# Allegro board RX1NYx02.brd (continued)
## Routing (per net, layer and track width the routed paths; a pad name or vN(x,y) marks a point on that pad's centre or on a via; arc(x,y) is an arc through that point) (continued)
PE_CPU_OCP_13_DN: length 58.9
  TOP w0.127: 237.46,-26.52 237.58,-26.39 239.44,-26.39 241.73,-28.68 242.76,-28.68 243.33,-28.11 243.33,-27.62 243.17,-26.72 243.33,-25.8 243.33,-25.46 242.69,-23.68 242.69,-21.4 242.28,-20.3 242.14,-19.5 242.14,-17.9 245.08,-14.96 245.34,-14.96 246.24,-15.12 248.1,-14.79 250.35,-15.19 252.6,-14.8 254.85,-15.19 257.11,-14.8 259.36,-15.19 260.65,-14.96 260.91,-14.96 261.87,-15.13 264.12,-14.74 266.37,-15.13 268.62,-14.74 269.91,-14.96 270.51,-14.96 270.97,-15.42 271.63,-15.42 272.37,-16.16 273.13,-16.16 273.69,-16.06 274.24,-16.16 274.78,-16.16 274.93,-16.31 P_OCP2.B59
  TOP w0.152: 237.46,-26.52 P_CPU_OCP_13_N.1
PE_CPU_OCP_13_DP: length 58.9
  TOP w0.127: 237.46,-25.96 237.58,-26.09 239.57,-26.09 241.86,-28.38 242.63,-28.38 243.03,-27.98 243.03,-27.65 242.86,-26.72 243.03,-25.78 243.03,-25.51 242.38,-23.74 242.38,-21.45 241.99,-20.38 241.84,-19.52 241.84,-17.78 244.96,-14.66 245.37,-14.66 246.24,-14.81 248.1,-14.49 250.35,-14.88 252.6,-14.49 254.85,-14.88 257.11,-14.49 259.36,-14.88 260.62,-14.66 260.93,-14.66 261.87,-14.82 264.12,-14.43 266.37,-14.82 268.62,-14.43 269.94,-14.66 270.64,-14.66 271.09,-15.12 271.75,-15.12 272.49,-15.85 273.1,-15.85 273.69,-15.75 274.27,-15.85 274.78,-15.85 274.93,-15.71 P_OCP2.B60
  TOP w0.152: 237.46,-25.96 P_CPU_OCP_13_P.1
PE_CPU_OCP_14_DN: length 58.9
  TOP w0.127: 257.69,-13.25 257.11,-13.14 256.51,-13.25 ; P_OCP2.B62 274.93,-14.51 274.78,-14.36 273.95,-14.36 273.53,-13.95 271.81,-13.95 271.2,-13.34 270.83,-13.34 ; 257.88,-13.28 259.36,-13.54 260.51,-13.34 261.05,-13.34 261.87,-13.48 264.12,-13.09 264.85,-13.21 ; 265.09,-13.26 266.37,-13.48 268.14,-13.17 ; 231.46,-9.09 231.59,-9.22 230.83,-13.55 231.02,-15.15 231.84,-15.97 234.3,-15.97 236.93,-13.34 237.44,-13.34 238.57,-13.14 240.82,-13.54 243.07,-13.14 244.19,-13.34 245.48,-13.34 246.24,-13.47 248.1,-13.14 250.35,-13.54 252.6,-13.14 254.85,-13.54 256.3,-13.29 ; 268.34,-13.14 268.62,-13.09 270.05,-13.34 270.62,-13.34
  TOP w0.152: P_CPU_OCP_14_N.1 231.46,-9.09 ; 268.14,-13.17 268.34,-13.14 ; 257.69,-13.25 257.88,-13.28 ; 264.85,-13.21 265.09,-13.26 ; 270.62,-13.34 270.83,-13.34 ; 256.3,-13.29 256.51,-13.25
PE_CPU_OCP_14_DP: length 58.9
  TOP w0.127: 270.62,-12.91 270.5,-13.03 270.08,-13.03 268.62,-12.78 268.42,-12.81 268.28,-12.71 ; 256.43,-12.86 256.54,-12.94 257.11,-12.83 257.63,-12.93 257.77,-12.82 ; 264.95,-12.79 264.8,-12.9 264.12,-12.78 261.87,-13.17 261.08,-13.03 260.48,-13.03 259.36,-13.23 258.08,-13.01 257.97,-12.86 ; 265.15,-12.83 265.25,-12.98 266.37,-13.17 267.97,-12.89 268.08,-12.74 ; 270.83,-12.91 270.95,-13.03 271.32,-13.03 271.93,-13.64 273.66,-13.64 274.07,-14.05 274.78,-14.05 274.93,-13.91 P_OCP2.B63 ; 232.02,-9.09 231.89,-9.22 231.14,-13.56 231.31,-15.01 231.97,-15.67 234.18,-15.67 236.81,-13.03 237.41,-13.03 238.57,-12.83 240.82,-13.23 243.07,-12.83 244.22,-13.03 245.51,-13.03 246.24,-13.16 248.1,-12.83 250.35,-13.23 252.6,-12.83 254.85,-13.23 256.17,-13 256.25,-12.89
  TOP w0.152: 256.25,-12.89 256.43,-12.86 ; P_CPU_OCP_14_P.1 232.02,-9.09 ; 268.08,-12.74 268.28,-12.71 ; 264.95,-12.79 265.15,-12.83 ; 270.62,-12.91 270.83,-12.91 ; 257.77,-12.82 257.97,-12.86
PE_CPU_OCP_15_DN: length 58.9
  TOP w0.127: 263.84,-8.22 263.92,-8.3 263.92,-8.64 264.22,-8.94 264.78,-8.94 265.41,-8.84 266.03,-8.94 266.46,-8.94 267.58,-8.75 268.71,-8.94 269.48,-8.94 269.61,-9.07 269.61,-9.78 269.41,-9.99 268.66,-9.99 267.58,-9.8 266.5,-9.99 266.24,-9.99 265.45,-10.12 264.66,-9.99 264.25,-9.99 263.94,-10.29 263.94,-10.68 263.82,-10.81 ; 266.81,-11.84 266.67,-11.74 265.95,-11.86 264.8,-11.66 264.25,-11.66 263.94,-11.36 263.94,-11.14 263.82,-11.01 ; 254.88,-9.86 254.75,-9.73 254.75,-9.32 253.55,-8.11 253.25,-6.4 253.36,-5.81 253.52,-5.68 254.26,-5.68 254.58,-6 254.59,-6.07 254.51,-6.56 254.51,-7.5 254.87,-7.86 255.71,-7.9 256.16,-7.53 256.28,-6.86 256.16,-6.18 256.16,-6.1 256.71,-5.54 257.03,-5.54 258.18,-5.75 259.33,-5.54 260.76,-5.54 261.91,-5.75 263.06,-5.54 263.88,-5.54 264.95,-5.73 266.03,-5.54 266.22,-5.54 266.4,-5.72 266.4,-6.08 266.46,-6.44 266.4,-6.81 266.4,-7.06 266.19,-7.27 266.09,-7.27 265.33,-7.14 264.58,-7.27 264.22,-7.27 263.92,-7.57 263.92,-7.84 263.84,-7.92 ; 272.71,-12.42 272.89,-12.42 273.03,-12.56 274.78,-12.56 274.93,-12.71 P_OCP2.B65 ; 267.01,-11.81 267.12,-11.66 267.75,-11.55 268.4,-11.66 268.91,-11.66 270.07,-11.86 270.86,-11.73 271.01,-11.83 ; 272.57,-12.27 272.57,-12.09 272.14,-11.66 271.98,-11.66 271.6,-11.6 271.31,-11.65 271.21,-11.79
  TOP w0.152: 263.84,-7.92 263.84,-8.22 ; 271.01,-11.83 271.21,-11.79 ; 263.82,-10.81 263.82,-11.01 ; P_CPU_OCP_15_N.1 254.88,-9.86 ; 272.57,-12.27 272.71,-12.42 ; 266.81,-11.84 267.01,-11.81
PE_CPU_OCP_15_DP: length 58.9
  TOP w0.127: P_OCP2.B66 274.93,-12.11 274.78,-12.25 273.16,-12.25 273.02,-12.11 ; 266.96,-11.38 267.75,-11.24 268.43,-11.36 268.94,-11.36 270.07,-11.56 270.97,-11.4 ; 264.22,-7.94 264.22,-7.7 264.35,-7.57 264.6,-7.57 265.33,-7.45 266.06,-7.57 266.32,-7.57 266.7,-7.19 266.7,-6.84 266.77,-6.44 266.7,-6.05 266.7,-5.59 266.35,-5.24 266,-5.24 264.95,-5.42 263.91,-5.24 263.04,-5.24 261.91,-5.44 260.78,-5.24 259.3,-5.24 258.18,-5.44 257.05,-5.24 256.59,-5.24 255.85,-5.97 255.85,-6.2 255.97,-6.86 255.88,-7.37 255.61,-7.59 255,-7.56 254.81,-7.37 254.81,-6.59 254.9,-6.07 254.87,-5.85 254.39,-5.37 253.41,-5.37 253.07,-5.65 252.95,-6.4 253.27,-8.26 254.45,-9.44 254.45,-9.73 254.32,-9.86 ; 271.12,-11.37 271.6,-11.29 272.01,-11.36 272.26,-11.36 272.88,-11.97 ; 264.22,-8.19 264.22,-8.51 264.35,-8.64 264.76,-8.64 265.41,-8.53 266.05,-8.64 266.43,-8.64 267.58,-8.44 268.74,-8.64 269.61,-8.64 269.91,-8.94 269.91,-9.91 269.53,-10.29 268.63,-10.29 267.58,-10.11 266.52,-10.29 266.27,-10.29 265.45,-10.43 264.64,-10.29 264.38,-10.29 264.25,-10.42 264.25,-10.8 ; 266.76,-11.41 265.95,-11.56 264.83,-11.36 264.38,-11.36 264.25,-11.23 264.25,-11.01
  TOP w0.152: P_CPU_OCP_15_P.1 254.32,-9.86 ; 270.97,-11.4 271.12,-11.37 ; 264.22,-7.94 264.22,-8.19 ; 264.25,-10.8 264.25,-11.01 ; 266.76,-11.41 266.96,-11.38 ; 272.88,-11.97 273.02,-12.11
PE_OCP_CPU_0_DN: length 104.7
  BOTTOM w0.127: 61.25,-19.6 64.2,-19.08 66.12,-19.42 ; 69.48,-25.91 69.35,-25.78 69.35,-25.36 69.72,-23.25 71.25,-21.72 72.76,-21.46 75.29,-21.91 ; 75.6,-18.89 76.58,-18.72 78.94,-19.13 79.82,-20.01 79.82,-21.07 79.11,-21.78 76.86,-22.18 75.53,-21.95 ; 66.36,-19.46 66.87,-19.55 69.37,-19.11 71.87,-19.55 75.39,-18.93 ; P_OCP1.A17 3.15,-31.5 3.3,-31.64 3.95,-31.64 4.66,-31.52 8.75,-32.24 12.46,-31.59 13.59,-31.79 15.87,-31.39 18.5,-31.85 20.93,-31.42 23.43,-31.86 27.22,-31.19 29.55,-31.6 39.02,-29.93 40.57,-30.21 44.04,-29.6 45.59,-28.05 46.42,-23.39 47.84,-21.97 54.32,-20.82 ; 61.07,-19.63 54.53,-20.79
  BOTTOM w0.152: 54.53,-20.79 54.32,-20.82 ; 75.29,-21.91 75.53,-21.95 ; 66.36,-19.46 66.12,-19.42 ; 75.6,-18.89 75.39,-18.93 ; 61.25,-19.6 61.07,-19.63 ; P_OCP_CPU_0_N.1 69.48,-25.91
PE_OCP_CPU_0_DP: length 104.7
  BOTTOM w0.127: 75.48,-19.35 75.33,-19.25 71.87,-19.86 69.37,-19.42 66.87,-19.86 66.41,-19.78 66.26,-19.88 ; 54.38,-21.23 54.25,-21.15 47.99,-22.25 46.7,-23.54 45.88,-28.19 44.19,-29.88 40.57,-30.52 39.02,-30.24 29.55,-31.91 27.22,-31.5 23.43,-32.17 20.93,-31.73 18.5,-32.16 15.87,-31.7 13.59,-32.1 12.46,-31.9 8.75,-32.55 4.66,-31.83 3.98,-31.95 3.3,-31.95 3.15,-32.1 P_OCP1.A18 ; 61.32,-20.03 61.42,-19.88 64.2,-19.39 65.96,-19.7 66.06,-19.85 ; 68.92,-25.91 69.05,-25.78 69.05,-25.33 69.44,-23.1 71.1,-21.44 72.76,-21.15 75.26,-21.59 75.4,-21.49 ; 61.12,-20.06 60.97,-19.96 54.7,-21.07 54.61,-21.19 ; 75.68,-19.32 75.78,-19.17 76.58,-19.03 78.8,-19.42 79.51,-20.14 79.51,-20.95 78.96,-21.5 76.86,-21.87 75.71,-21.67 75.6,-21.52
  BOTTOM w0.152: 75.68,-19.32 75.48,-19.35 ; 66.26,-19.88 66.06,-19.85 ; 75.4,-21.49 75.6,-21.52 ; 61.32,-20.03 61.12,-20.06 ; P_OCP_CPU_0_P.1 68.92,-25.91 ; 54.61,-21.19 54.38,-21.23
PE_OCP_CPU_1_DN: length 104.7
  BOTTOM w0.127: 86.68,-30.86 86.58,-31.01 85.9,-31.13 80.46,-30.17 78.58,-29.84 77.38,-30.05 74.88,-29.61 72.38,-30.05 69.88,-29.61 67.37,-30.05 66.65,-29.92 66.55,-29.77 ; 48.88,-29.96 48.77,-30.11 46.79,-30.46 40.19,-31.62 38.66,-31.36 28.42,-33.16 27.15,-32.94 23.92,-33.51 20.9,-32.98 18.52,-33.4 16.3,-33.01 15.84,-33.01 9.69,-34.09 6.05,-33.44 5.06,-33.44 4.39,-33.33 3.73,-33.44 3.3,-33.44 3.15,-33.3 P_OCP1.A20 ; 49.08,-29.93 49.22,-30.03 50.39,-29.83 51.11,-29.83 52.37,-30.05 54.87,-29.61 55.74,-29.76 55.89,-29.66 ; 66.35,-29.74 66.2,-29.84 64.87,-29.61 62.37,-30.05 59.87,-29.61 59.25,-29.72 59.15,-29.65 ; 91.78,-20.58 91.91,-20.7 91.91,-21.16 90.58,-28.79 87.72,-30.8 87.03,-30.93 86.88,-30.82 ; 58.87,-29.69 58.8,-29.79 57.37,-30.05 56.19,-29.84 56.09,-29.69
  BOTTOM w0.152: 59.15,-29.65 58.87,-29.69 ; 49.08,-29.93 48.88,-29.96 ; 86.88,-30.82 86.68,-30.86 ; 66.55,-29.77 66.35,-29.74 ; 56.09,-29.69 55.89,-29.66 ; P_OCP_CPU_1_N.1 91.78,-20.58
PE_OCP_CPU_1_DP: length 104.7
  BOTTOM w0.127: 86.96,-31.25 87.84,-31.09 90.86,-28.97 92.21,-21.18 92.21,-20.7 92.34,-20.58 ; 58.93,-30.08 57.37,-30.36 55.99,-30.11 ; 66.28,-30.16 64.87,-29.91 62.37,-30.36 59.87,-29.91 59.21,-30.03 ; 66.45,-30.19 67.37,-30.36 69.88,-29.91 72.38,-30.36 74.88,-29.91 77.38,-30.36 78.58,-30.14 85.9,-31.43 86.72,-31.29 ; 49.12,-30.36 50.42,-30.13 51.09,-30.13 52.37,-30.36 54.87,-29.91 55.82,-30.08 ; 48.95,-30.39 40.19,-31.93 38.66,-31.66 28.42,-33.47 27.15,-33.25 23.92,-33.82 20.9,-33.29 18.52,-33.71 16.27,-33.31 15.86,-33.31 9.69,-34.4 6.03,-33.75 5.03,-33.75 4.39,-33.64 3.76,-33.75 3.3,-33.75 3.15,-33.9 P_OCP1.A21
  BOTTOM w0.152: P_OCP_CPU_1_P.1 92.34,-20.58 ; 49.12,-30.36 48.95,-30.39 ; 66.45,-30.19 66.28,-30.16 ; 55.99,-30.11 55.82,-30.08 ; 59.21,-30.03 58.93,-30.08 ; 86.96,-31.25 86.72,-31.29
PE_OCP_CPU_2_DN: length 104.8
  BOTTOM w0.127: 74.91,-42.77 74.79,-42.89 74.2,-42.89 71.44,-43.37 70.4,-44.41 70.4,-44.87 70.31,-45.37 70.56,-46.8 70.56,-47 69.93,-47.64 69.02,-47.64 68.6,-47.22 68.38,-45.91 68.38,-45.47 67.91,-42.81 68.35,-40.3 67.91,-37.8 68.45,-34.73 68.2,-33.31 66.38,-31.49 64.19,-31.1 61.69,-31.55 59.19,-31.1 56.69,-31.55 54.18,-31.1 51.68,-31.55 50.43,-31.32 49.7,-31.32 40.12,-33.01 38.83,-32.79 37.37,-33.04 34.87,-35.54 34.87,-38.77 32.36,-41.28 30.96,-41.53 28.69,-41.13 27.2,-41.39 24.76,-40.97 21.45,-41.54 18.68,-41.06 15.85,-41.56 13.2,-41.09 7.9,-35.79 4.28,-35.15 3.65,-35.26 3.32,-35.26 3.15,-35.1 P_OCP1.A23
  BOTTOM w0.152: 74.91,-42.77 P_OCP_CPU_2_N.1
PE_OCP_CPU_2_DP: length 104.8
  BOTTOM w0.127: 74.91,-43.33 74.79,-43.2 74.22,-43.2 71.59,-43.66 70.78,-44.47 70.62,-45.37 70.87,-46.77 70.87,-47.13 70.05,-47.94 68.9,-47.94 68.32,-47.36 68.07,-45.94 68.07,-45.5 67.6,-42.81 68.04,-40.3 67.6,-37.8 68.14,-34.73 67.92,-33.45 66.23,-31.77 64.19,-31.41 61.69,-31.85 59.19,-31.41 56.69,-31.85 54.18,-31.41 51.68,-31.85 50.41,-31.63 49.73,-31.63 40.12,-33.32 38.83,-33.1 37.52,-33.32 35.18,-35.67 35.18,-38.89 32.51,-41.56 30.96,-41.84 28.69,-41.44 27.2,-41.7 24.76,-41.27 21.45,-41.85 18.68,-41.37 15.85,-41.87 13.05,-41.38 7.75,-36.07 4.28,-35.46 3.68,-35.57 3.28,-35.57 3.15,-35.7 P_OCP1.A24
  BOTTOM w0.152: 74.91,-43.33 P_OCP_CPU_2_P.1
PE_OCP_CPU_3_DN: length 104.7
  BOTTOM w0.127: P_OCP1.A26 3.15,-36.9 3.3,-37.04 3.97,-37.04 4.5,-36.95 7.27,-37.44 12.35,-42.51 16.71,-43.28 19.91,-42.72 22.02,-43.09 24.52,-42.65 26.71,-43.04 28.49,-42.72 30.62,-43.1 33.84,-42.53 35.35,-42.8 37.85,-42.36 40.36,-42.8 44.04,-42.15 45.85,-40.34 45.85,-39.83 45.26,-36.48 45.55,-34.85 47.01,-33.39 49.24,-33 51.77,-33.45 54.27,-33 56.44,-33.39 59.18,-36.13 59.18,-37.04 56.69,-39.53 56.69,-40.14 56.9,-41.32 56.47,-43.75 56.91,-46.25 56.35,-49.46 56.55,-50.62 57.15,-51.21 58.29,-51.21 58.96,-50.55 59.14,-49.54 58.32,-44.93 58.59,-43.44 59.13,-42.89 60.16,-42.89 61.27,-43.09 62.38,-42.89 63.36,-42.89 63.48,-42.77
  BOTTOM w0.152: 63.48,-42.77 P_OCP_CPU_3_N.1
PE_OCP_CPU_3_DP: length 104.7
  BOTTOM w0.127: P_OCP1.A27 3.15,-37.5 3.3,-37.35 3.99,-37.35 4.5,-37.26 5.81,-37.49 7.12,-37.72 12.2,-42.8 16.71,-43.59 19.91,-43.03 22.02,-43.4 24.52,-42.96 26.71,-43.35 28.49,-43.03 30.62,-43.41 33.84,-42.84 35.35,-43.11 37.85,-42.67 40.36,-43.11 44.18,-42.44 46.15,-40.47 46.15,-39.81 45.57,-36.48 45.83,-35 47.15,-33.68 49.24,-33.31 51.77,-33.75 54.27,-33.31 56.3,-33.67 58.88,-36.25 58.88,-36.91 56.39,-39.4 56.39,-40.16 56.59,-41.32 56.16,-43.75 56.6,-46.25 56.04,-49.46 56.27,-50.76 57.02,-51.52 58.42,-51.52 59.24,-50.7 59.45,-49.54 58.63,-44.93 58.87,-43.59 59.26,-43.2 60.13,-43.2 61.27,-43.4 62.4,-43.2 63.36,-43.2 63.48,-43.33
  BOTTOM w0.152: 63.48,-43.33 P_OCP_CPU_3_P.1
PE_OCP_CPU_4_DN: length 104.7
  BOTTOM w0.127: P_OCP1.A30 3.15,-42.71 3.33,-42.88 3.82,-42.88 4.92,-42.69 5.34,-42.69 6.09,-42.82 6.51,-42.75 7.87,-41.38 8.94,-41.38 10.36,-42.81 10.36,-43.33 10.14,-44.59 10.4,-46.04 12.01,-47.66 13.16,-47.66 13.42,-47.4 13.51,-46.87 13.31,-45.72 13.31,-45.14 14.1,-44.35 14.6,-44.35 17.2,-44.81 19.44,-44.41 21.22,-44.73 22.24,-45.74 22.57,-47.65 22.15,-50.1 22.15,-50.78 22.63,-51.26 24.03,-51.26 24.8,-50.49 24.8,-50.34 24.8,-50.32 24.19,-46.88 24.39,-45.77 25.52,-44.64 28.6,-44.1 32.79,-44.84 33.52,-45.57 34.09,-48.8 33.81,-50.41 33.81,-50.73 34.14,-51.06 35.23,-51.06 35.98,-50.31 36.1,-49.65 35.64,-47.02 35.96,-45.17 37.11,-44.02 38.42,-44.02 41.66,-44.59 44.31,-44.13 44.78,-44.13 45.55,-44.9 45.55,-45.52 44.97,-48.81 45.32,-50.78 45.95,-51.42 46.71,-51.42 47.29,-50.83 47.29,-50.52 46.97,-48.67 47.41,-46.16 46.82,-42.8 47.06,-41.44 47.64,-40.86 48.5,-40.86 50.31,-42.68 51.57,-42.89 51.93,-42.89 52.05,-42.77
  BOTTOM w0.152: P_OCP_CPU_4_N.1 52.05,-42.77
PE_OCP_CPU_4_DP: length 104.7
  BOTTOM w0.127: P_OCP1.A31 3.15,-43.31 3.27,-43.19 3.85,-43.19 4.94,-42.99 5.31,-42.99 6.09,-43.13 6.66,-43.03 8,-41.69 8.81,-41.69 10.06,-42.93 10.06,-43.31 9.83,-44.59 10.11,-46.18 11.89,-47.96 13.28,-47.96 13.7,-47.54 13.82,-46.87 13.61,-45.69 13.61,-45.27 14.22,-44.66 14.57,-44.66 17.2,-45.12 19.44,-44.72 21.08,-45.01 21.95,-45.89 22.26,-47.65 21.84,-50.07 21.84,-50.91 22.51,-51.57 24.16,-51.57 25.1,-50.62 25.1,-50.33 25.1,-50.28 24.5,-46.88 24.67,-45.92 25.67,-44.93 28.6,-44.41 32.65,-45.12 33.24,-45.71 33.78,-48.8 33.5,-50.39 33.5,-50.86 34.01,-51.37 35.36,-51.37 36.27,-50.45 36.41,-49.65 35.95,-47.02 36.25,-45.32 37.24,-44.33 38.4,-44.33 41.66,-44.9 44.34,-44.43 44.65,-44.43 45.24,-45.02 45.24,-45.5 44.66,-48.81 45.03,-50.93 45.82,-51.72 46.84,-51.72 47.6,-50.96 47.6,-50.49 47.28,-48.67 47.72,-46.16 47.13,-42.8 47.34,-41.59 47.76,-41.17 48.38,-41.17 50.17,-42.96 51.55,-43.2 51.93,-43.2 52.05,-43.33
  BOTTOM w0.152: P_OCP_CPU_4_P.1 52.05,-43.33
PE_OCP_CPU_5_DN: length 104.8
  BOTTOM w0.127: P_OCP1.A33 3.15,-44.51 3.33,-44.68 4.01,-44.68 5.02,-44.51 6.97,-44.85 15.06,-52.94 17.92,-53.44 21.43,-52.82 23.93,-53.26 26.81,-52.76 29.31,-53.2 32.34,-52.66 34.84,-53.1 37.2,-52.69 39.7,-53.13 42.2,-52.69 44.95,-53.17 47.46,-52.73 49.71,-53.13 52.21,-52.69 54.71,-53.13 57.21,-52.69 59.71,-53.13 62.21,-52.69 65.32,-53.24 67.92,-55.84 68.31,-58.06 67.78,-61.09 68.22,-63.59 67.78,-66.1 68.22,-68.6 67.87,-70.61 67.87,-71.61 68.83,-72.57 69.85,-72.57 70.13,-72.3 70.97,-67.52 72.38,-66.11 74.43,-65.75 74.79,-65.75 74.91,-65.63
  BOTTOM w0.152: P_OCP_CPU_5_N.1 74.91,-65.63
PE_OCP_CPU_5_DP: length 104.8
  BOTTOM w0.127: P_OCP1.A34 3.15,-45.11 3.27,-44.99 4.03,-44.99 5.02,-44.82 6.82,-45.13 14.91,-53.22 17.92,-53.75 21.43,-53.13 23.93,-53.57 26.81,-53.07 29.31,-53.51 32.34,-52.97 34.84,-53.41 37.2,-53 39.7,-53.44 42.2,-53 44.95,-53.48 47.46,-53.04 49.71,-53.44 52.21,-53 54.71,-53.44 57.21,-53 59.71,-53.44 62.21,-53 65.17,-53.52 67.64,-55.99 68,-58.06 67.47,-61.09 67.91,-63.59 67.47,-66.1 67.91,-68.6 67.56,-70.58 67.56,-71.74 68.71,-72.88 69.98,-72.88 70.41,-72.44 71.25,-67.67 72.52,-66.4 74.46,-66.06 74.79,-66.06 74.91,-66.19
  BOTTOM w0.152: P_OCP_CPU_5_P.1 74.91,-66.19
PE_OCP_CPU_6_DN: length 104.7
  BOTTOM w0.127: P_OCP1.A36 3.15,-46.31 3.3,-46.45 4.08,-46.45 4.82,-46.33 6.94,-46.69 14.66,-54.42 17.71,-54.95 21.48,-54.29 23.98,-54.73 27.07,-54.19 29.57,-54.63 31.68,-54.26 34.18,-54.7 37.29,-54.15 39.79,-54.59 42.46,-54.12 44.96,-54.56 47.19,-54.17 49.69,-54.61 52.06,-54.19 54.56,-54.63 57.32,-54.15 60,-54.62 60.5,-55.12 60.5,-55.91 57.78,-58.64 56.29,-67.11 56.66,-69.23 56.22,-71.73 56.63,-74.09 57.4,-74.86 58.01,-74.86 58.78,-74.09 59.15,-71.97 58.31,-67.15 58.51,-65.98 59.21,-65.28 60.01,-65.28 62.71,-65.75 63.36,-65.75 63.48,-65.63
  BOTTOM w0.152: 63.48,-65.63 P_OCP_CPU_6_N.1
PE_OCP_CPU_6_DP: length 104.7
  BOTTOM w0.127: 63.48,-66.19 63.36,-66.06 62.69,-66.06 59.98,-65.59 59.33,-65.59 58.8,-66.13 58.61,-67.15 59.46,-71.97 59.07,-74.24 58.14,-75.16 57.28,-75.16 56.35,-74.24 55.91,-71.73 56.35,-69.23 55.98,-67.11 57.5,-58.49 60.2,-55.79 60.2,-55.25 59.85,-54.9 57.32,-54.46 54.56,-54.94 52.06,-54.5 49.69,-54.92 47.19,-54.48 44.96,-54.87 42.46,-54.43 39.79,-54.9 37.29,-54.46 34.18,-55.01 31.68,-54.56 29.57,-54.94 27.07,-54.5 23.98,-55.04 21.48,-54.6 17.71,-55.26 14.51,-54.7 6.79,-46.98 4.82,-46.64 4.11,-46.76 3.3,-46.76 3.15,-46.91 P_OCP1.A37
  BOTTOM w0.152: 63.48,-66.19 P_OCP_CPU_6_P.1
PE_OCP_CPU_7_DN: length 104.8
  BOTTOM w0.127: 52.05,-65.63 51.93,-65.75 51.34,-65.75 49.75,-66.03 47.75,-68.03 47.75,-69.32 46.69,-70.39 45.8,-70.39 45.09,-69.69 44.72,-67.56 45.44,-63.5 45,-60.99 45.44,-58.49 45.21,-57.22 43.81,-55.81 42.67,-55.61 40.17,-56.05 38.49,-55.76 37.65,-55.9 36.22,-57.34 35.97,-58.72 36.54,-61.92 36.1,-64.43 36.63,-67.47 35.99,-71.13 35.41,-71.71 34.21,-71.71 33.52,-71.01 33.32,-69.88 33.65,-68.01 33.31,-66.11 33.75,-63.61 33.36,-61.36 33.89,-58.33 33.68,-57.13 32.46,-55.91 31.22,-55.69 29.18,-56.05 26.68,-55.61 23.55,-56.16 21.05,-55.72 17.6,-56.33 14.04,-55.7 6.81,-48.48 4.77,-48.12 3.79,-48.29 3.34,-48.29 3.15,-48.11 P_OCP1.A39
  BOTTOM w0.152: P_OCP_CPU_7_N.1 52.05,-65.63
PE_OCP_CPU_7_DP: length 104.8
  BOTTOM w0.127: 52.05,-66.19 51.93,-66.06 51.37,-66.06 49.9,-66.32 48.06,-68.15 48.06,-69.45 46.81,-70.69 45.67,-70.69 44.81,-69.83 44.41,-67.56 45.13,-63.5 44.69,-60.99 45.13,-58.49 44.93,-57.36 43.66,-56.09 42.67,-55.92 40.17,-56.36 38.49,-56.07 37.8,-56.19 36.5,-57.48 36.28,-58.72 36.85,-61.92 36.41,-64.43 36.94,-67.47 36.27,-71.28 35.53,-72.02 34.09,-72.02 33.23,-71.16 33.01,-69.88 33.34,-68.01 33,-66.11 33.44,-63.61 33.05,-61.36 33.58,-58.33 33.39,-57.28 32.31,-56.19 31.22,-56 29.18,-56.36 26.68,-55.92 23.55,-56.47 21.05,-56.03 17.6,-56.64 13.89,-55.99 6.67,-48.76 4.77,-48.43 3.82,-48.6 3.33,-48.6 3.22,-48.71 P_OCP1.A40
  BOTTOM w0.152: P_OCP_CPU_7_P.1 52.05,-66.19
PE_OCP_CPU_8_DN: length 104.8
  BOTTOM w0.127: P_OCP2.A44 274.93,-25.31 274.78,-25.16 274.29,-25.16 273.69,-25.06 271.68,-25.41 270.01,-27.07 269.7,-28.84 270.25,-31.94 269.81,-34.45 270.09,-36.05 269.53,-39.2 270.89,-46.9 270.89,-47.31 270.41,-47.79 269.72,-47.79 269.13,-47.2 267.87,-40.09 267.52,-39.8 267.22,-39.81 266.88,-40.15 266.88,-41.04 267.92,-46.97 267.52,-47.37 266.66,-47.42 266.14,-47.01 265.14,-41.31 264.87,-41.08 264.37,-41.11 264.29,-41.11 264.08,-41.31 264.08,-42.14 264.75,-45.98 264.51,-47.37 264.35,-47.52 264.2,-47.67 255.98,-49.12 250.05,-48.08 243.09,-49.3 240.47,-48.84 235.46,-49.72 231.53,-49.03 229.29,-49.42 227.41,-49.09 226.55,-49.24 226.15,-49.24 226.03,-49.37
  BOTTOM w0.152: P_OCP_CPU_8_N.1 226.03,-50.73 226.03,-49.37
PE_OCP_CPU_8_DP: length 104.7
  BOTTOM w0.127: P_OCP2.A45 274.93,-24.71 274.78,-24.85 274.31,-24.85 273.69,-24.75 271.53,-25.12 269.73,-26.93 269.39,-28.84 269.94,-31.94 269.5,-34.45 269.78,-36.05 269.22,-39.2 270.59,-46.93 270.59,-47.19 270.29,-47.49 269.85,-47.49 269.41,-47.05 268.15,-39.93 267.63,-39.49 267.09,-39.51 266.57,-40.02 266.57,-41.07 267.59,-46.87 267.39,-47.07 266.76,-47.11 266.42,-46.84 265.42,-41.15 264.97,-40.77 264.36,-40.8 264.16,-40.8 263.78,-41.19 263.78,-42.17 264.44,-45.98 264.22,-47.22 264.06,-47.39 255.98,-48.81 250.05,-47.77 243.09,-48.99 240.47,-48.53 235.46,-49.41 231.53,-48.72 229.29,-49.11 227.41,-48.79 226.52,-48.94 226.15,-48.94 226.03,-48.81
  BOTTOM w0.152: 226.03,-48.81 226.03,-47.45 P_OCP_CPU_8_P.1
PE_OCP_CPU_9_DN: length 104.8
  BOTTOM w0.127: 214.6,-49.37 214.72,-49.24 215.41,-49.24 216.4,-49.42 217.94,-49.15 218.72,-49.28 219.64,-50.2 219.83,-51.31 219.11,-55.43 219.39,-57.04 220.24,-57.89 221.26,-57.89 221.93,-57.23 222.04,-56.56 221.64,-54.29 222.09,-51.79 221.7,-49.6 222.14,-47.1 221.56,-43.82 222.22,-40.06 222.84,-39.45 223.41,-39.45 224.93,-39.72 227.39,-39.28 229.9,-39.72 232.4,-39.28 234.22,-39.6 237.32,-39.06 239.16,-39.38 241.69,-38.94 249.25,-40.27 253.63,-39.5 254.91,-39.72 256.34,-39.47 259.57,-40.04 265.12,-39.06 267.53,-36.65 268.47,-31.31 268.01,-28.7 268.34,-26.81 271.64,-23.52 273.49,-23.19 274.44,-23.36 274.78,-23.36 274.93,-23.51 P_OCP2.A47
  BOTTOM w0.152: 214.6,-49.37 P_OCP_CPU_9_N.1
PE_OCP_CPU_9_DP: length 104.7
  BOTTOM w0.127: 214.6,-48.81 214.72,-48.94 215.44,-48.94 216.4,-49.11 217.94,-48.84 218.87,-49 219.92,-50.05 220.14,-51.31 219.41,-55.43 219.67,-56.89 220.37,-57.59 221.13,-57.59 221.64,-57.08 221.73,-56.56 221.33,-54.29 221.78,-51.79 221.39,-49.6 221.83,-47.1 221.25,-43.82 221.94,-39.92 222.71,-39.14 223.44,-39.14 224.93,-39.41 227.39,-38.97 229.9,-39.41 232.4,-38.97 234.22,-39.29 237.32,-38.75 239.16,-39.07 241.69,-38.63 249.25,-39.96 253.63,-39.19 254.91,-39.41 256.34,-39.16 259.57,-39.73 264.97,-38.78 267.25,-36.5 268.16,-31.31 267.7,-28.7 268.06,-26.66 271.49,-23.23 273.49,-22.89 274.47,-23.05 274.78,-23.05 274.93,-22.91 P_OCP2.A48
  BOTTOM w0.152: 214.6,-48.81 P_OCP_CPU_9_P.1
PE_OCP_CPU_10_DN: length 104.7
  BOTTOM w0.127: 203.17,-26.51 203.29,-26.38 203.67,-26.38 207.3,-25.76 207.65,-25.41 207.65,-24.64 208.75,-23.54 209.49,-23.54 210.19,-24.24 210.19,-24.59 209.93,-26.04 210.32,-28.25 209.6,-32.32 210.06,-34.93 211.99,-36.86 219.23,-38.14 222.11,-37.63 224.61,-38.07 227.11,-37.63 229.61,-38.07 232.11,-37.63 234.61,-38.07 237.12,-37.63 238.92,-37.95 241.35,-37.52 249.12,-38.89 254.19,-38 254.63,-38.07 255.75,-37.87 259.77,-38.58 264.46,-37.76 266.19,-36.02 266.8,-32.56 266.23,-29.34 266.85,-25.84 270.84,-21.85 273.35,-21.42 274.17,-21.56 274.78,-21.56 274.93,-21.71 P_OCP2.A50
  BOTTOM w0.152: 203.17,-26.51 P_OCP_CPU_10_N.1
PE_OCP_CPU_10_DP: length 104.7
  BOTTOM w0.127: 203.17,-25.95 203.29,-26.08 203.65,-26.08 207.15,-25.47 207.34,-25.28 207.34,-24.51 208.62,-23.23 209.61,-23.23 210.49,-24.11 210.49,-24.62 210.24,-26.04 210.63,-28.25 209.91,-32.32 210.34,-34.78 212.14,-36.58 219.23,-37.83 222.11,-37.32 224.61,-37.76 227.11,-37.32 229.61,-37.76 232.11,-37.32 234.61,-37.76 237.12,-37.32 238.92,-37.64 241.35,-37.21 249.12,-38.58 254.19,-37.69 254.63,-37.76 255.75,-37.56 259.77,-38.27 264.31,-37.47 265.91,-35.87 266.49,-32.57 265.92,-29.34 266.56,-25.7 270.69,-21.57 273.35,-21.11 274.19,-21.25 274.78,-21.25 274.93,-21.11 P_OCP2.A51
  BOTTOM w0.152: 203.17,-25.95 P_OCP_CPU_10_P.1
PE_OCP_CPU_11_DN: length 104.8
  BOTTOM w0.127: P_OCP2.A53 274.93,-19.91 274.78,-19.76 274.01,-19.76 270.4,-20.39 265.47,-25.32 264.36,-31.58 264.74,-33.75 264.43,-35.53 263.36,-36.6 260.16,-37.17 255.85,-36.41 255.36,-36.5 254.64,-36.37 249.2,-37.33 241.56,-35.98 239.06,-36.42 236.56,-35.98 234.06,-36.42 231.56,-35.98 229.06,-36.42 226.56,-35.98 223.95,-36.44 222.49,-36.18 221.89,-35.59 221.27,-32.07 221.53,-30.64 221,-27.67 221.44,-25.17 221.08,-23.14 221.63,-20.07 221.55,-19.65 220.8,-18.9 219.68,-18.9 219.09,-19.49 218.9,-21.77 219.63,-26 219.63,-26.76 218.71,-27.69 218.11,-27.69 217.13,-26.71 215.25,-26.38 214.72,-26.38 214.6,-26.51
  BOTTOM w0.152: 214.6,-26.51 P_OCP_CPU_11_N.1
PE_OCP_CPU_11_DP: length 104.8
  BOTTOM w0.127: 214.6,-25.95 214.72,-26.08 215.28,-26.08 217.27,-26.43 218.24,-27.39 218.58,-27.39 219.33,-26.64 219.33,-26.02 218.59,-21.79 218.79,-19.36 219.56,-18.59 220.93,-18.59 221.84,-19.5 221.94,-20.07 221.39,-23.14 221.75,-25.17 221.31,-27.67 221.84,-30.64 221.58,-32.07 222.18,-35.44 222.63,-35.9 223.95,-36.13 226.56,-35.67 229.06,-36.11 231.56,-35.67 234.06,-36.11 236.56,-35.67 239.06,-36.11 241.56,-35.67 249.2,-37.02 254.64,-36.06 255.36,-36.19 255.85,-36.1 260.16,-36.86 263.21,-36.32 264.15,-35.39 264.43,-33.75 264.05,-31.58 265.18,-25.17 270.25,-20.1 273.99,-19.45 274.78,-19.45 274.93,-19.31 P_OCP2.A54
  BOTTOM w0.152: 214.6,-25.95 P_OCP_CPU_11_P.1
PE_OCP_CPU_12_DN: length 104.7
  BOTTOM w0.127: P_OCP2.A56 274.93,-18.11 274.78,-17.96 274.36,-17.96 273.47,-17.81 265.35,-19.22 264.29,-20.28 264.29,-20.74 264.7,-23.06 264.49,-24.24 263.4,-25.33 262.84,-25.33 260.92,-24.99 258.15,-25.48 256.29,-25.15 255.35,-24.21 255.35,-23.3 255.8,-20.67 255.54,-19.2 254.76,-18.42 254.13,-18.42 253.54,-19 253.54,-20.28 253.72,-21.28 253.32,-23.53 253.61,-25.16 253.56,-26 253.47,-26.29 251.93,-27.82 250.97,-27.99 248.47,-27.55 245.63,-28.05 244.97,-27.94 243.92,-26.88 243.92,-25.93 244.11,-24.84 243.69,-22.46 244.24,-19.33 244.16,-18.87 243.71,-18.42 242.95,-18.42 242.1,-19.27 241.93,-20.24 242.46,-23.26 242.1,-25.31 242.24,-26.12 242.24,-26.42 241.73,-26.93 237.43,-27.69 234.48,-27.17 233.24,-25.93 232.77,-23.25 233.1,-21.35 232.89,-20.18 232.01,-19.29 231.47,-19.29 230.66,-20.1 230.46,-21.22 230.94,-23.93 230.7,-25.29 229.39,-26.6 228.5,-26.75 226.39,-26.38 226.15,-26.38 226.03,-26.51
  BOTTOM w0.152: P_OCP_CPU_12_N.1 226.03,-26.51
PE_OCP_CPU_12_DP: length 104.8
  BOTTOM w0.127: 226.03,-25.95 226.15,-26.08 226.41,-26.08 228.5,-26.44 229.25,-26.31 230.42,-25.14 230.63,-23.93 230.15,-21.22 230.38,-19.95 231.34,-18.98 232.13,-18.98 233.18,-20.03 233.41,-21.35 233.08,-23.25 233.52,-25.78 234.63,-26.89 237.43,-27.38 241.59,-26.64 241.94,-26.3 241.94,-26.14 241.79,-25.31 242.15,-23.26 241.62,-20.24 241.82,-19.12 242.82,-18.12 243.84,-18.12 244.44,-18.72 244.55,-19.33 244,-22.46 244.42,-24.84 244.22,-25.96 244.22,-26.75 245.12,-27.65 245.63,-27.74 248.47,-27.24 250.97,-27.68 251.79,-27.54 253.2,-26.12 253.26,-25.95 253.3,-25.18 253.01,-23.53 253.41,-21.28 253.24,-20.31 253.24,-18.88 254,-18.12 254.89,-18.12 255.83,-19.06 256.11,-20.67 255.65,-23.33 255.65,-24.09 256.43,-24.87 258.15,-25.17 260.92,-24.68 262.86,-25.02 263.27,-25.02 264.21,-24.09 264.39,-23.06 263.98,-20.77 263.98,-20.15 265.2,-18.93 273.47,-17.5 274.38,-17.65 274.78,-17.65 274.93,-17.51 P_OCP2.A57
  BOTTOM w0.152: P_OCP_CPU_12_P.1 226.03,-25.95
PE_OCP_CPU_13_DN: length 104.8
  BOTTOM w0.127: 260.27,-16.93 260.12,-16.82 259.53,-16.93 257.03,-16.49 256.45,-16.59 256.35,-16.74 ; 247.2,-17.16 247.31,-17.09 247.97,-17.2 250.18,-16.81 252.68,-17.25 256,-16.67 256.15,-16.77 ; P_OCP2.A59 274.93,-16.31 274.78,-16.16 274.31,-16.16 273.77,-16.07 270.28,-16.67 267.97,-16.26 266.74,-16.48 266.63,-16.63 ; 246.94,-17.12 246.86,-17.01 246.2,-16.89 244.73,-17.15 240.9,-16.47 238.39,-16.91 235.95,-16.48 233.45,-16.92 230.77,-16.45 229.08,-16.75 227.3,-16.44 224.49,-16.93 221.99,-16.49 218.98,-17.02 216.48,-16.58 213.98,-17.02 211.48,-16.58 208.98,-17.02 206.09,-16.51 203.59,-16.95 201.18,-16.53 199.71,-16.79 196.21,-16.17 192.67,-16.79 184.91,-15.42 184.58,-15.42 184.18,-15.83 184.18,-16.67 185.94,-18.43 186.17,-19.75 186.17,-20.4 186.3,-20.52 ; 262.6,-16.92 262.74,-16.82 263.8,-17 266.29,-16.56 266.43,-16.67 ; 262.4,-16.88 262.29,-16.74 261.45,-16.59 260.57,-16.74 260.47,-16.89
  BOTTOM w0.152: 247.2,-17.16 246.94,-17.12 ; 260.47,-16.89 260.27,-16.93 ; 256.35,-16.74 256.15,-16.77 ; 186.3,-20.52 P_OCP_CPU_13_N.1 ; 262.6,-16.92 262.4,-16.88 ; 266.63,-16.63 266.43,-16.67
PE_OCP_CPU_13_DP: length 104.8
  BOTTOM w0.127: P_OCP2.A60 274.93,-15.71 274.78,-15.85 274.33,-15.85 273.77,-15.76 270.28,-16.36 267.97,-15.96 266.6,-16.2 ; 185.74,-20.52 185.86,-20.4 185.86,-19.77 185.66,-18.58 183.87,-16.8 183.87,-15.7 184.46,-15.12 184.93,-15.12 192.67,-16.48 196.21,-15.86 199.71,-16.48 201.18,-16.22 203.59,-16.64 206.09,-16.2 208.98,-16.71 211.48,-16.27 213.98,-16.71 216.48,-16.27 218.98,-16.71 221.99,-16.18 224.49,-16.62 227.3,-16.13 229.08,-16.44 230.77,-16.14 233.45,-16.61 235.95,-16.17 238.39,-16.6 240.9,-16.16 244.73,-16.84 246.2,-16.58 247.02,-16.72 ; 260.2,-16.5 259.53,-16.62 257.03,-16.18 252.68,-16.94 250.18,-16.5 247.97,-16.89 247.23,-16.76 ; 266.37,-16.24 263.8,-16.69 262.66,-16.49 ; 260.43,-16.46 261.45,-16.28 262.43,-16.45
  BOTTOM w0.152: 260.2,-16.5 260.43,-16.46 ; 266.37,-16.24 266.6,-16.2 ; 262.43,-16.45 262.66,-16.49 ; 247.02,-16.72 247.23,-16.76 ; P_OCP_CPU_13_P.1 185.74,-20.52
PE_OCP_CPU_14_DN: length 104.7
  BOTTOM w0.127: 198.2,-14.2 197.73,-14.12 196.98,-13.37 196.59,-13.37 195.96,-14.01 ; 206.54,-14.79 208.87,-15.2 209.19,-15.2 209.2,-15.2 210.72,-14.93 213.23,-15.37 215.73,-14.93 218.23,-15.37 221.23,-14.84 224.41,-15.4 227.15,-14.92 228.96,-15.24 230.74,-14.93 233.24,-15.37 235.74,-14.93 238.24,-15.37 240.74,-14.93 244.36,-15.57 245.87,-15.3 247.25,-15.55 249.56,-15.14 252.06,-15.58 256.2,-14.85 258.7,-15.29 260.75,-14.93 263.25,-15.37 267.47,-14.63 269.33,-14.96 273.55,-14.22 274.34,-14.36 274.78,-14.36 274.93,-14.51 P_OCP2.A62 ; 202.45,-14.95 203.42,-15.12 205.92,-14.68 206.32,-14.75 ; 202.17,-14.9 198.5,-14.26 ; 195.75,-14.22 194.95,-15.01 194.44,-15.1 193.77,-14.98 192.11,-13.33 ; 191.99,-13.21 191.81,-13.03 191.02,-12.89 190.26,-13.02 188.92,-14.36 188.07,-14.51 187.17,-14.35 186.16,-14.01 185.01,-12.86 184.83,-11.83 185.06,-10.5 185.86,-9.7 185.86,-9.22 185.74,-9.09
  BOTTOM w0.152: 195.75,-14.22 195.96,-14.01 ; 198.2,-14.2 198.5,-14.26 ; P_OCP_CPU_14_N.1 185.74,-9.09 ; 202.17,-14.9 202.45,-14.95 ; 191.99,-13.21 192.11,-13.33 ; 206.32,-14.75 206.54,-14.79
PE_OCP_CPU_14_DP: length 104.8
  BOTTOM w0.127: 202.5,-14.55 202.58,-14.67 203.42,-14.82 205.92,-14.37 206.27,-14.44 206.41,-14.34 ; 192.43,-13.04 192.43,-13.22 193.91,-14.7 194.44,-14.79 194.81,-14.73 195.48,-14.05 195.48,-13.87 ; 195.62,-13.73 195.8,-13.73 196.46,-13.07 197.11,-13.07 197.88,-13.84 198.17,-13.89 198.3,-13.8 ; 186.3,-9.09 186.17,-9.22 186.17,-9.82 185.35,-10.64 185.14,-11.83 185.3,-12.71 186.33,-13.74 187.25,-14.06 188.07,-14.2 188.77,-14.08 190.11,-12.74 191.02,-12.58 191.96,-12.74 192.11,-12.89 192.29,-12.89 ; 198.53,-13.84 198.62,-13.97 202.13,-14.59 202.25,-14.5 ; P_OCP2.A63 274.93,-13.91 274.78,-14.05 274.37,-14.05 273.55,-13.91 269.33,-14.65 267.47,-14.32 263.25,-15.06 260.75,-14.62 258.7,-14.98 256.2,-14.54 252.06,-15.27 249.56,-14.83 247.25,-15.24 245.87,-14.99 244.36,-15.26 240.74,-14.62 238.24,-15.06 235.74,-14.62 233.24,-15.06 230.74,-14.62 228.96,-14.93 227.15,-14.61 224.41,-15.09 221.23,-14.53 218.23,-15.06 215.73,-14.62 213.23,-15.06 210.72,-14.62 209.14,-14.9 208.89,-14.9 206.72,-14.52 206.63,-14.38
  BOTTOM w0.152: 198.3,-13.8 198.53,-13.84 ; 195.48,-13.87 195.62,-13.73 ; 192.29,-12.89 192.43,-13.04 ; 202.25,-14.5 202.5,-14.55 ; P_OCP_CPU_14_P.1 186.3,-9.09 ; 206.41,-14.34 206.63,-14.38
PE_OCP_CPU_15_DN: length 104.8
  BOTTOM w0.127: 215.47,-13.37 216.27,-13.23 216.84,-13.33 ; 217.07,-13.37 217.76,-13.49 218.19,-13.49 219.2,-12.48 219.31,-11.84 219.04,-10.26 219.48,-7.76 219.25,-6.48 219.25,-6.18 219.84,-5.59 220.73,-5.59 221.24,-6.11 221.49,-7.53 220.85,-11.19 221.09,-12.56 221.97,-13.45 223.49,-13.71 226.1,-13.25 229.12,-13.79 230.26,-13.59 230.92,-12.92 231.3,-10.76 230.71,-7.39 230.89,-6.35 231.55,-5.7 232.18,-5.7 232.61,-6.13 232.61,-6.45 232.36,-7.88 232.83,-10.53 232.55,-12.09 232.66,-12.72 232.66,-12.83 233.1,-13.27 233.5,-13.27 234.58,-13.08 236.93,-13.49 239.43,-13.05 241.93,-13.49 242.91,-13.32 246.13,-13.89 248.6,-13.45 252.11,-14.07 256.04,-13.38 257.6,-13.65 259.7,-13.28 262.74,-13.82 267.72,-12.94 269.27,-13.21 273.57,-12.47 274.12,-12.56 274.78,-12.56 274.93,-12.71 P_OCP2.A65 ; 215.18,-13.43 213.77,-13.67 211.58,-13.29 211.09,-12.8 ; 210.13,-11.83 210.91,-12.62 ; 209.4,-11.11 209.99,-11.69 ; 209.25,-10.96 208.72,-10.43 208.72,-9.22 208.6,-9.09
  BOTTOM w0.152: 216.84,-13.33 217.07,-13.37 ; 209.25,-10.96 209.4,-11.11 ; 209.99,-11.69 210.13,-11.83 ; P_OCP_CPU_15_N.1 208.6,-9.09 ; 210.91,-12.62 211.09,-12.8 ; 215.18,-13.43 215.47,-13.37
PE_OCP_CPU_15_DP: length 104.8
  BOTTOM w0.127: 210.3,-11.39 210.12,-11.39 209.71,-10.99 209.71,-10.81 ; 217.15,-12.97 217.23,-13.09 217.78,-13.19 218.06,-13.19 218.92,-12.33 219,-11.84 218.73,-10.26 219.17,-7.76 218.95,-6.51 218.95,-6.05 219.71,-5.29 220.85,-5.29 221.52,-5.96 221.8,-7.53 221.16,-11.19 221.37,-12.41 222.12,-13.16 223.49,-13.4 226.1,-12.94 229.12,-13.48 230.11,-13.3 230.64,-12.78 230.99,-10.76 230.4,-7.39 230.61,-6.2 231.42,-5.39 232.31,-5.39 232.92,-6 232.92,-6.48 232.67,-7.88 233.14,-10.53 232.86,-12.09 232.97,-12.69 232.97,-12.71 233.22,-12.96 233.48,-12.96 234.58,-12.77 236.93,-13.18 239.43,-12.74 241.93,-13.18 242.91,-13.01 246.13,-13.58 248.6,-13.14 252.11,-13.76 256.04,-13.07 257.6,-13.34 259.7,-12.97 262.74,-13.51 267.72,-12.63 269.27,-12.9 273.57,-12.16 274.14,-12.25 274.78,-12.25 274.93,-12.11 P_OCP2.A66 ; 209.57,-10.66 209.39,-10.66 209.03,-10.31 209.03,-9.22 209.16,-9.09 ; 210.44,-11.54 210.44,-11.72 211.08,-12.35 211.26,-12.35 ; 215.1,-13.05 215.03,-13.14 213.77,-13.36 211.73,-13.01 211.4,-12.68 211.4,-12.5 ; 216.91,-12.93 216.78,-13.01 216.27,-12.92 215.48,-13.06 215.38,-13
  BOTTOM w0.152: P_OCP_CPU_15_P.1 209.16,-9.09 ; 215.1,-13.05 215.38,-13 ; 210.3,-11.39 210.44,-11.54 ; 216.91,-12.93 217.15,-12.97 ; 211.26,-12.35 211.4,-12.5 ; 209.57,-10.66 209.71,-10.81
SET2DIL_85_BOT: length 203.2
  BOTTOM w0.102: 224.67,-95.36 224.67,-95.66
  BOTTOM w0.127: J_S2D_BOT.2 123.51,-95.28 123.59,-95.36 224.67,-95.36 ; J_S2D_BOT.3 123.49,-95.73 123.56,-95.66 224.67,-95.66
SET2DIL_85_TOP: length 203.2
  TOP w0.102: 224.67,-86.47 224.67,-86.77
  TOP w0.127: 224.67,-86.47 123.59,-86.47 123.51,-86.39 J_S2D_TOP.3 ; J_S2D_TOP.2 123.49,-86.84 123.56,-86.77 224.67,-86.77
SMA_2IN_BOT_DN: length 50.9
  BOTTOM w0.127: 244.6,42.69 244.48,42.82 244.22,42.82 241.73,42.15 236.82,43.47 231.91,42.15 227.01,43.47 222.1,42.15 217.19,43.47 212.46,42.22 210.15,42.82 209.04,42.82 208.92,42.69
  BOTTOM w0.152: 208.92,42.69 P_SMA_BOT_2IN_DN_1.1 ; P_SMA_BOT_2IN_DN_2.1 244.6,42.69
SMA_2IN_BOT_DP: length 50.9
  BOTTOM w0.127: 208.92,43.25 209.04,43.13 210.19,43.13 212.46,42.54 217.19,43.78 222.1,42.47 227.01,43.78 231.91,42.47 236.82,43.78 241.73,42.47 244.18,43.13 244.48,43.13 244.6,43.25
  BOTTOM w0.152: 208.92,43.25 P_SMA_BOT_2IN_DP_2.1 ; P_SMA_BOT_2IN_DP_1.1 244.6,43.25
SMA_2IN_TOP_DN: length 50.9
  TOP w0.127: 68.71,57.17 68.58,57.3 68.37,57.3 65.87,56.63 60.97,57.95 56.06,56.63 51.15,57.95 46.24,56.63 41.34,57.95 36.59,56.69 34.25,57.3 33.15,57.3 33.02,57.17
  TOP w0.152: 33.02,57.17 P_SMA_TOP_2IN_DN_1.1 ; P_SMA_TOP_2IN_DN_2.1 68.71,57.17
SMA_2IN_TOP_DP: length 50.9
  TOP w0.127: 33.02,57.73 33.15,57.6 34.29,57.6 36.59,57.01 41.34,58.26 46.24,56.95 51.15,58.26 56.06,56.95 60.97,58.26 65.87,56.95 68.33,57.6 68.58,57.6 68.71,57.73
  TOP w0.152: P_SMA_TOP_2IN_DP_2.1 68.71,57.73 ; 33.02,57.73 P_SMA_TOP_2IN_DP_1.1
SMA_5IN_BOT_DN: length 127.1
  BOTTOM w0.127: 12.7,43.25 12.83,43.13 13.12,43.13 13.33,43.07 16,43.78 20.91,42.47 25.81,43.78 30.72,42.47 35.63,43.78 40.53,42.47 45.44,43.78 50.35,42.47 55.25,43.78 60.16,42.47 65.07,43.78 69.98,42.47 74.88,43.78 79.79,42.47 84.7,43.78 89.6,42.47 94.51,43.78 99.42,42.47 104.32,43.78 109.23,42.47 114.14,43.78 119.04,42.47 121.5,43.13 121.79,43.13 121.92,43.25
  BOTTOM w0.152: 12.7,43.25 P_SMA_BOT_5IN_DN_1.1 ; P_SMA_BOT_5IN_DN_2.1 121.92,43.25
SMA_5IN_BOT_DP: length 127.1
  BOTTOM w0.127: 12.7,42.69 12.83,42.82 13.08,42.82 13.34,42.76 16,43.47 20.91,42.15 25.81,43.47 30.72,42.15 35.63,43.47 40.53,42.15 45.44,43.47 50.35,42.15 55.25,43.47 60.16,42.15 65.07,43.47 69.98,42.15 74.88,43.47 79.79,42.15 84.7,43.47 89.6,42.15 94.51,43.47 99.42,42.15 104.32,43.47 109.23,42.15 114.14,43.47 119.04,42.15 121.54,42.82 121.79,42.82 121.92,42.69
  BOTTOM w0.152: 12.7,42.69 P_SMA_BOT_5IN_DP_1.1 ; P_SMA_BOT_5IN_DP_2.1 121.92,42.69
SMA_5IN_TOP_DN: length 127.1
  TOP w0.127: 155.7,57.73 155.83,57.6 156.08,57.6 156.32,57.66 159,56.95 163.91,58.26 168.82,56.95 173.72,58.26 178.63,56.95 183.54,58.26 188.44,56.95 193.35,58.26 198.26,56.95 203.16,58.26 208.07,56.95 212.98,58.26 217.88,56.95 222.79,58.26 227.7,56.95 232.61,58.26 237.51,56.95 242.42,58.26 247.33,56.95 252.23,58.26 257.14,56.95 262.05,58.26 264.5,57.6 264.79,57.6 264.92,57.73
  TOP w0.152: P_SMA_TOP_5IN_DN_2.1 264.92,57.73 ; 155.7,57.73 P_SMA_TOP_5IN_DN_1.1
SMA_5IN_TOP_DP: length 127.1
  TOP w0.127: 264.92,57.17 264.79,57.3 264.46,57.3 262.05,57.95 257.14,56.63 252.23,57.95 247.33,56.63 242.42,57.95 237.51,56.63 232.61,57.95 227.7,56.63 222.79,57.95 217.88,56.63 212.98,57.95 208.07,56.63 203.16,57.95 198.26,56.63 193.35,57.95 188.44,56.63 183.54,57.95 178.63,56.63 173.72,57.95 168.82,56.63 163.91,57.95 159,56.63 156.31,57.35 156.12,57.3 155.83,57.3 155.7,57.17
  TOP w0.152: P_SMA_TOP_5IN_DP_2.1 264.92,57.17 ; 155.7,57.17 P_SMA_TOP_5IN_DP_1.1
SMA_10IN_BOT_DN: length 254.1
  BOTTOM w0.127: 12.7,14.3 12.83,14.17 13.08,14.17 13.32,14.11 16.01,14.83 20.92,13.51 25.82,14.83 30.73,13.51 35.64,14.83 40.54,13.51 45.45,14.83 50.36,13.51 55.26,14.83 60.17,13.51 65.08,14.83 69.99,13.51 74.89,14.83 79.8,13.51 84.71,14.83 89.61,13.51 94.52,14.83 99.43,13.51 104.33,14.83 109.24,13.51 114.15,14.83 119.05,13.51 123.96,14.83 128.87,13.51 133.77,14.83 138.68,13.51 143.59,14.83 148.5,13.51 153.4,14.83 158.31,13.51 163.22,14.83 168.12,13.51 173.03,14.83 177.94,13.51 182.84,14.83 187.75,13.51 192.66,14.83 197.56,13.51 202.47,14.83 207.38,13.51 212.29,14.83 217.19,13.51 222.1,14.83 227.01,13.51 231.91,14.83 236.82,13.51 241.73,14.83 244.18,14.17 244.48,14.17 244.6,14.3
  BOTTOM w0.152: P_SMA_BOT_10IN_DN_1.1 244.6,14.3 ; 12.7,14.3 P_SMA_BOT_10IN_DN_2.1
SMA_10IN_BOT_DP: length 254.1
  BOTTOM w0.127: 12.7,13.74 12.83,13.87 13.04,13.87 13.32,13.79 16.01,14.51 20.92,13.2 25.82,14.51 30.73,13.2 35.64,14.51 40.54,13.2 45.45,14.51 50.36,13.2 55.26,14.51 60.17,13.2 65.08,14.51 69.99,13.2 74.89,14.51 79.8,13.2 84.71,14.51 89.61,13.2 94.52,14.51 99.43,13.2 104.33,14.51 109.24,13.2 114.15,14.51 119.05,13.2 123.96,14.51 128.87,13.2 133.77,14.51 138.68,13.2 143.59,14.51 148.5,13.2 153.4,14.51 158.31,13.2 163.22,14.51 168.12,13.2 173.03,14.51 177.94,13.2 182.84,14.51 187.75,13.2 192.66,14.51 197.56,13.2 202.47,14.51 207.38,13.2 212.29,14.51 217.19,13.2 222.1,14.51 227.01,13.2 231.91,14.51 236.82,13.2 241.73,14.51 244.14,13.87 244.48,13.87 244.6,13.74
  BOTTOM w0.152: P_SMA_BOT_10IN_DP_1.1 244.6,13.74 ; 12.7,13.74 P_SMA_BOT_10IN_DP_2.1
SMA_10IN_TOP_DN: length 254.1
  TOP w0.127: 264.92,28.78 264.79,28.65 264.54,28.65 264.3,28.59 261.61,29.31 256.71,27.99 251.8,29.31 246.89,27.99 241.99,29.31 237.08,27.99 232.17,29.31 227.26,27.99 222.36,29.31 217.45,27.99 212.54,29.31 207.64,27.99 202.73,29.31 197.82,27.99 192.92,29.31 188.01,27.99 183.1,29.31 178.2,27.99 173.29,29.31 168.38,27.99 163.47,29.31 158.57,27.99 153.66,29.31 148.75,27.99 143.85,29.31 138.94,27.99 134.03,29.31 129.13,27.99 124.22,29.31 119.31,27.99 114.41,29.31 109.5,27.99 104.59,29.31 99.69,27.99 94.78,29.31 89.87,27.99 84.96,29.31 80.06,27.99 75.15,29.31 70.24,27.99 65.34,29.31 60.43,27.99 55.52,29.31 50.62,27.99 45.71,29.31 40.8,27.99 35.9,29.31 33.44,28.65 33.15,28.65 33.02,28.78
  TOP w0.152: 33.02,28.78 P_SMA_TOP_10IN_DN_1.1 ; P_SMA_TOP_10IN_DN_2.1 264.92,28.78
SMA_10IN_TOP_DP: length 254.1
  TOP w0.127: 264.92,28.22 264.79,28.34 264.58,28.34 264.3,28.27 261.61,28.99 256.71,27.68 251.8,28.99 246.89,27.68 241.99,28.99 237.08,27.68 232.17,28.99 227.26,27.68 222.36,28.99 217.45,27.68 212.54,28.99 207.64,27.68 202.73,28.99 197.82,27.68 192.92,28.99 188.01,27.68 183.1,28.99 178.2,27.68 173.29,28.99 168.38,27.68 163.47,28.99 158.57,27.68 153.66,28.99 148.75,27.68 143.85,28.99 138.94,27.68 134.03,28.99 129.13,27.68 124.22,28.99 119.31,27.68 114.41,28.99 109.5,27.68 104.59,28.99 99.69,27.68 94.78,28.99 89.87,27.68 84.96,28.99 80.06,27.68 75.15,28.99 70.24,27.68 65.34,28.99 60.43,27.68 55.52,28.99 50.62,27.68 45.71,28.99 40.8,27.68 35.9,28.99 33.48,28.34 33.15,28.34 33.02,28.22
  TOP w0.152: 33.02,28.22 P_SMA_TOP_10IN_DP_1.1 ; P_SMA_TOP_10IN_DP_2.1 264.92,28.22
V_3P3AUX_1: length 34.8
  TOP w0.102: 93.99,-59.99 C166.1 ; 93.7,-63.2 C16.1
  TOP w0.254: v1(107.79,-31.63) 107.56,-31.86 C1.1 107.05,-32.26 ; U2.5 82.67,-43.71 C3.2 82.66,-43.31 v1(82.41,-43.06) ; U6.5 88.7,-42.76 88.99,-43.06 C8.2 89.4,-43.44 v1(89.65,-43.69) ; R13.2 108.44,-33.08 ; R13.2 108.44,-33.73 ; R13.2 108.77,-33.4 ; U24.13 93.7,-63.2 ; v1(89.65,-50.04) 89.4,-49.79 C2.2 88.99,-49.41 88.7,-49.11 U1.5 ; R167.1 v1(92.19,-61.37) ; 108.62,-34.73 R11.2 ; R11.2 109.05,-34.29 ; R11.2 108.62,-33.86 ; C166.1 v1(94,-60.64) ; R15.2 v1(98.03,-36.33) ; v1(82.41,-39.88) 82.66,-40.13 C4.2 82.67,-40.53 U3.5 ; v1(82.41,-51.06) 82.66,-51.31 C5.2 82.67,-51.71 U5.5 ; U7.5 82.67,-46.88 C9.2 82.66,-46.48 v1(82.41,-46.23) ; U26.5 93.99,-59.99 ; R5.2 v1(9.89,-6.35) ; C16.1 v1(94.34,-63.2)
  TOP w0.381: R9.2 v1(88.02,-38.74) ; P_OCP1.B11 5.97,-27.9 v1(7.11,-29.04) ; 107.05,-32.26 U4.8 ; R17.2 v1(91.96,-51.82)
  TOP w0.508: v1(97.01,-25.91) 97.44,-26.34 R158.2 ; R20.1 v1(99.68,-15.24) ; R164.2 10.28,-68.79 v1(9.94,-68.46)
  vias: v1(9.87,-20.4) v1(9.87,-21.29) v1(9.89,-22.1) v1(9.89,-22.99) v1(98.16,-50.3) v1(99.04,-50.3) v1(99.93,-50.3) v1(100.82,-50.3) v1(101.71,-50.3) v1(102.6,-50.3) v1(103.49,-50.3) v1(104.38,-50.3) v1(109.33,-33.4) v1(109.33,-34.29)
V_3P3AUX_2: length 32.3
  TOP w0.102: 186.39,-63.15 C85.1 ; 186.68,-59.3 C167.1
  TOP w0.254: v1(170.29,-49.1) 170.52,-48.87 C75.1 171.04,-48.46 ; U23.5 195.41,-33.84 C83.2 195.42,-34.24 v1(195.67,-34.49) ; U18.5 195.41,-40.19 C78.2 195.42,-40.59 v1(195.67,-40.84) ; R79.2 v1(268.19,-74.37) ; U25.13 186.39,-63.15 ; U21.5 195.41,-29.02 C79.2 195.42,-29.42 v1(195.67,-29.67) ; v1(195.67,-37.67) 195.42,-37.42 C77.2 195.41,-37.02 U19.5 ; v1(188.44,-37.03) 188.69,-37.28 C82.2 189.09,-37.67 189.39,-37.96 U22.5 ; C167.1 v1(186.69,-59.95) ; U17.5 189.39,-31.61 189.09,-31.32 C76.2 188.69,-30.93 v1(188.44,-30.68) ; U27.5 186.68,-59.3 ; R92.2 v1(180.05,-44.4) ; C85.1 v1(187.03,-63.15) ; R168.1 v1(184.89,-61.32)
  TOP w0.381: R94.2 v1(186.12,-28.91) ; R86.2 v1(190.06,-41.99) ; v1(270.61,-52.15) 271.29,-52.83 P_OCP2.B11 ; U20.8 171.04,-48.46
  TOP w0.508: R160.2 178.48,-54.38 v1(178.91,-54.81) ; R97.1 v1(178.31,-65.48) ; R166.2 v1(267.97,-6.81)
  vias: v1(168.75,-46.43) v1(168.75,-47.32) v1(173.7,-30.43) v1(174.59,-30.43) v1(175.48,-30.43) v1(176.37,-30.43) v1(177.26,-30.43) v1(178.15,-30.43) v1(179.04,-30.43) v1(179.93,-30.43) v1(268.48,-57.74) v1(268.48,-58.5) v1(268.48,-59.52) v1(268.48,-60.28)
V_12V_1: length 2.3
  TOP w0.254: C150.2 102.78,-24.72 R154.2
  TOP w0.508: C150.2 v1(101.71,-25.28)
  vias: v1(5.57,-22.61) v1(5.57,-23.63) v1(5.57,-24.64)
V_12V_2: length 2.3
  TOP w0.254: C157.2 173.14,-56 R156.2
  TOP w0.508: C157.2 v1(174.21,-55.45)
  vias: v1(270,-60.28) v1(272.41,-55.96) v1(272.41,-57.1) v1(272.43,-58.24)
Z_42.5_BOT: length 152.4
  BOTTOM w0.152: 95.89,-92.79 95.12,-92.79 94.78,-93.13 83.94,-95.04 81.44,-94.6 78.94,-95.04 76.44,-94.6 73.93,-95.04 71.43,-94.6 68.93,-95.04 66.43,-94.6 63.93,-95.04 61.43,-94.6 58.93,-95.04 56.43,-94.6 53.92,-95.04 51.42,-94.6 48.92,-95.04 46.42,-94.6 43.92,-95.04 41.99,-94.7 39.88,-95.08 39.24,-95.08 38.48,-94.31 38.48,-93.84 38.62,-93.68 38.95,-93.62 40.54,-93.9 43.04,-93.46 45.54,-93.9 48.04,-93.46 50.54,-93.9 53.05,-93.46 55.55,-93.9 58.05,-93.46 60.55,-93.9 63.05,-93.46 65.55,-93.9 68.05,-93.46 70.56,-93.9 73.06,-93.46 75.56,-93.9 78.06,-93.46 79.31,-93.68 79.63,-93.68 80.01,-93.3 80.01,-92.92 79.69,-92.6 78.08,-92.32 75.58,-92.76 73.08,-92.31 70.58,-92.76 68.08,-92.31 65.58,-92.76 63.08,-92.31 60.58,-92.76 58.07,-92.31 55.57,-92.76 53.07,-92.31 50.57,-92.76 48.07,-92.31 45.57,-92.76 43.07,-92.31 40.41,-92.78 37.76,-92.31 35.26,-92.76 32.76,-92.31 31.5,-92.54 Z_42.5_BOT_END.2
Z_42.5_TOP: length 152.5
  TOP w0.152: Z_42.5_TOP.2 23.53,-89.74 28.23,-90.57 30.74,-90.13 41.11,-91.96 43.42,-91.55 45.92,-91.99 48.43,-91.55 50.93,-91.99 53.43,-91.55 55.93,-91.99 58.43,-91.55 60.93,-91.99 63.43,-91.55 65.94,-91.99 68.44,-91.55 70.94,-91.99 73.44,-91.55 75.94,-91.99 78.3,-91.58 78.74,-91.14 78.74,-90.76 78.09,-90.1 76.3,-89.79 72.44,-90.47 69.94,-90.03 67.44,-90.47 64.94,-90.03 62.44,-90.47 59.94,-90.03 57.44,-90.47 54.93,-90.03 52.43,-90.47 49.93,-90.03 47.43,-90.47 44.93,-90.03 42.43,-90.47 37.97,-89.68 37.34,-89.06 37.34,-88.73 37.89,-88.17 41.8,-87.48 46.5,-88.31 49.01,-87.87 51.51,-88.31 54.01,-87.87 56.51,-88.31 59.01,-87.87 61.51,-88.31 64.01,-87.87 66.52,-88.31 69.02,-87.87 71.52,-88.31 74.02,-87.87 76.52,-88.31 79.02,-87.87 81.18,-88.25 82.17,-89.23 87.29,-90.12 Z_42.5_TOP_END.2
Z_85D_BOT_DN: length 152.4
  BOTTOM w0.127: Z_85D_BOT_END.3 108.36,-97.06 106.88,-97.06 106.58,-96.75 106.58,-96.7 106.45,-96.57 105.82,-96.57 105.69,-96.7 105.69,-97.23 105.38,-97.54 104.5,-97.54 104.19,-97.23 104.19,-96.7 104.06,-96.57 103.43,-96.57 103.3,-96.7 103.3,-97.23 103,-97.54 102.11,-97.54 101.8,-97.23 101.8,-96.7 101.68,-96.57 101.04,-96.57 100.91,-96.7 100.91,-97.23 100.61,-97.54 99.72,-97.54 99.41,-97.23 99.41,-96.7 99.29,-96.57 98.65,-96.57 98.53,-96.7 98.53,-97.23 98.22,-97.54 97.33,-97.54 97.03,-97.23 97.03,-96.7 96.9,-96.57 96.26,-96.57 96.14,-96.7 96.14,-97.23 95.83,-97.54 94.94,-97.54 94.64,-97.23 94.64,-96.7 94.51,-96.57 93.88,-96.57 93.75,-96.7 93.75,-97.23 93.44,-97.54 92.56,-97.54 92.25,-97.23 92.25,-96.7 92.12,-96.57 91.49,-96.57 91.36,-96.7 91.36,-97.23 91.06,-97.54 90.17,-97.54 89.86,-97.23 89.86,-96.7 89.74,-96.57 89.1,-96.57 88.98,-96.7 88.98,-97.23 88.67,-97.54 87.78,-97.54 87.48,-97.23 87.48,-96.7 87.35,-96.57 86.71,-96.57 86.59,-96.7 86.59,-97.23 86.28,-97.54 85.39,-97.54 85.09,-97.23 85.09,-96.7 84.96,-96.57 84.33,-96.57 84.2,-96.7 84.2,-97.23 83.89,-97.54 83.01,-97.54 82.7,-97.23 82.7,-96.7 82.57,-96.57 81.94,-96.57 81.81,-96.7 81.81,-97.23 81.51,-97.54 80.62,-97.54 80.31,-97.23 80.31,-96.7 80.19,-96.57 79.55,-96.57 79.42,-96.7 79.42,-97.23 79.12,-97.54 78.23,-97.54 77.93,-97.23 77.93,-96.7 77.8,-96.57 77.16,-96.57 77.04,-96.7 77.04,-97.23 76.73,-97.54 75.84,-97.54 75.54,-97.23 75.54,-96.7 75.41,-96.57 74.78,-96.57 74.65,-96.7 74.65,-97.23 74.34,-97.54 73.46,-97.54 73.15,-97.23 73.15,-96.7 73.02,-96.57 72.39,-96.57 72.26,-96.7 72.26,-97.23 71.96,-97.54 71.07,-97.54 70.76,-97.23 70.76,-96.7 70.64,-96.57 70,-96.57 69.87,-96.7 69.87,-97.23 69.57,-97.54 68.68,-97.54 68.38,-97.23 68.38,-96.7 68.25,-96.57 67.61,-96.57 67.49,-96.7 67.49,-97.23 67.18,-97.54 66.29,-97.54 65.99,-97.23 65.99,-96.7 65.86,-96.57 65.23,-96.57 65.1,-96.7 65.1,-97.23 64.79,-97.54 63.91,-97.54 63.6,-97.23 63.6,-96.7 63.47,-96.57 62.84,-96.57 62.71,-96.7 62.71,-97.23 62.41,-97.54 61.52,-97.54 61.21,-97.23 61.21,-96.7 61.09,-96.57 60.45,-96.57 60.32,-96.7 60.32,-97.23 60.02,-97.54 59.13,-97.54 58.83,-97.23 58.83,-96.7 58.7,-96.57 58.06,-96.57 57.94,-96.7 57.94,-97.23 57.63,-97.54 56.74,-97.54 56.44,-97.23 56.44,-96.7 56.31,-96.57 55.68,-96.57 55.55,-96.7 55.55,-97.23 55.24,-97.54 54.36,-97.54 54.05,-97.23 54.05,-96.7 53.92,-96.57 53.29,-96.57 53.16,-96.7 53.16,-97.23 52.86,-97.54 51.97,-97.54 51.66,-97.23 51.66,-96.7 51.54,-96.57 50.9,-96.57 50.77,-96.7 50.77,-97.23 50.47,-97.54 49.58,-97.54 49.27,-97.23 49.27,-96.7 49.15,-96.57 48.51,-96.57 48.39,-96.7 48.39,-97.23 48.08,-97.54 47.19,-97.54 46.89,-97.23 46.89,-96.7 46.76,-96.57 46.13,-96.57 46,-96.7 46,-97.23 45.69,-97.54 44.81,-97.54 44.5,-97.23 44.5,-96.7 44.37,-96.57 43.74,-96.57 43.61,-96.7 43.61,-97.23 43.31,-97.54 42.42,-97.54 42.11,-97.23 42.11,-96.7 41.99,-96.57 41.35,-96.57 41.22,-96.7 41.22,-97.23 40.92,-97.54 40.03,-97.54 39.72,-97.23 39.72,-96.62 39.6,-96.5 38.96,-96.5 38.84,-96.62 38.84,-97.23 38.53,-97.54 37.64,-97.54 37.34,-97.23 37.34,-96.62 37.21,-96.5 36.57,-96.5 36.45,-96.62 36.45,-97.23 36.14,-97.54 35.25,-97.54 34.95,-97.23 34.95,-96.62 34.82,-96.5 34.19,-96.5 34.06,-96.62 34.06,-97.23 33.75,-97.54 32.87,-97.54 32.56,-97.23 32.56,-96.62 32.43,-96.5 31.8,-96.5 31.67,-96.62 31.67,-97.23 31.37,-97.54 30.48,-97.54 30.17,-97.23 30.17,-96.62 30.05,-96.5 29.41,-96.5 29.29,-96.62 29.29,-97.23 28.98,-97.54 28.09,-97.54 27.79,-97.23 27.79,-96.62 27.66,-96.5 27.02,-96.5 26.9,-96.62 26.9,-97.23 26.59,-97.54 25.7,-97.54 25.4,-97.23 25.4,-96.62 25.27,-96.5 24.64,-96.5 24.51,-96.62 24.51,-97.23 24.2,-97.54 23.32,-97.54 23.01,-97.23 23.01,-96.62 22.88,-96.5 22.25,-96.5 22.12,-96.62 22.12,-97.23 21.82,-97.54 20.93,-97.54 20.62,-97.23 20.62,-96.62 20.5,-96.5 19.86,-96.5 19.73,-96.62 19.73,-97.23 19.43,-97.54 18.54,-97.54 18.24,-97.23 18.24,-96.62 18.11,-96.5 17.47,-96.5 17.35,-96.62 17.35,-97.23 17.04,-97.54 16.15,-97.54 15.67,-97.06 12.94,-97.06 12.76,-97.23 Z_85D_BOT.4
Z_85D_BOT_DP: length 152.4
  BOTTOM w0.127: Z_85D_BOT_END.2 108.36,-96.75 107.01,-96.75 106.88,-96.62 106.88,-96.57 106.58,-96.27 105.69,-96.27 105.38,-96.57 105.38,-97.11 105.26,-97.23 104.62,-97.23 104.49,-97.11 104.49,-96.57 104.19,-96.27 103.3,-96.27 103,-96.57 103,-97.11 102.87,-97.23 102.23,-97.23 102.11,-97.11 102.11,-96.57 101.8,-96.27 100.91,-96.27 100.61,-96.57 100.61,-97.11 100.48,-97.23 99.85,-97.23 99.72,-97.11 99.72,-96.57 99.41,-96.27 98.53,-96.27 98.22,-96.57 98.22,-97.11 98.09,-97.23 97.46,-97.23 97.33,-97.11 97.33,-96.57 97.03,-96.27 96.14,-96.27 95.83,-96.57 95.83,-97.11 95.71,-97.23 95.07,-97.23 94.94,-97.11 94.94,-96.57 94.64,-96.27 93.75,-96.27 93.45,-96.57 93.45,-97.11 93.32,-97.23 92.68,-97.23 92.56,-97.11 92.56,-96.57 92.25,-96.27 91.36,-96.27 91.06,-96.57 91.06,-97.11 90.93,-97.23 90.3,-97.23 90.17,-97.11 90.17,-96.57 89.86,-96.27 88.98,-96.27 88.67,-96.57 88.67,-97.11 88.54,-97.23 87.91,-97.23 87.78,-97.11 87.78,-96.57 87.48,-96.27 86.59,-96.27 86.28,-96.57 86.28,-97.11 86.16,-97.23 85.52,-97.23 85.39,-97.11 85.39,-96.57 85.09,-96.27 84.2,-96.27 83.9,-96.57 83.9,-97.11 83.77,-97.23 83.13,-97.23 83.01,-97.11 83.01,-96.57 82.7,-96.27 81.81,-96.27 81.51,-96.57 81.51,-97.11 81.38,-97.23 80.75,-97.23 80.62,-97.11 80.62,-96.57 80.31,-96.27 79.43,-96.27 79.12,-96.57 79.12,-97.11 78.99,-97.23 78.36,-97.23 78.23,-97.11 78.23,-96.57 77.93,-96.27 77.04,-96.27 76.73,-96.57 76.73,-97.11 76.61,-97.23 75.97,-97.23 75.84,-97.11 75.84,-96.57 75.54,-96.27 74.65,-96.27 74.34,-96.57 74.34,-97.11 74.22,-97.23 73.58,-97.23 73.46,-97.11 73.46,-96.57 73.15,-96.27 72.26,-96.27 71.96,-96.57 71.96,-97.11 71.83,-97.23 71.2,-97.23 71.07,-97.11 71.07,-96.57 70.76,-96.27 69.87,-96.27 69.57,-96.57 69.57,-97.11 69.44,-97.23 68.81,-97.23 68.68,-97.11 68.68,-96.57 68.37,-96.27 67.49,-96.27 67.18,-96.57 67.18,-97.11 67.05,-97.23 66.42,-97.23 66.29,-97.11 66.29,-96.57 65.99,-96.27 65.1,-96.27 64.79,-96.57 64.79,-97.11 64.67,-97.23 64.03,-97.23 63.91,-97.11 63.91,-96.57 63.6,-96.27 62.71,-96.27 62.41,-96.57 62.41,-97.11 62.28,-97.23 61.64,-97.23 61.52,-97.11 61.52,-96.57 61.21,-96.27 60.32,-96.27 60.02,-96.57 60.02,-97.11 59.89,-97.23 59.26,-97.23 59.13,-97.11 59.13,-96.57 58.82,-96.27 57.94,-96.27 57.63,-96.57 57.63,-97.11 57.5,-97.23 56.87,-97.23 56.74,-97.11 56.74,-96.57 56.44,-96.27 55.55,-96.27 55.24,-96.57 55.24,-97.11 55.12,-97.23 54.48,-97.23 54.35,-97.11 54.35,-96.57 54.05,-96.27 53.16,-96.27 52.86,-96.57 52.86,-97.11 52.73,-97.23 52.09,-97.23 51.97,-97.11 51.97,-96.57 51.66,-96.27 50.77,-96.27 50.47,-96.57 50.47,-97.11 50.34,-97.23 49.71,-97.23 49.58,-97.11 49.58,-96.57 49.27,-96.27 48.39,-96.27 48.08,-96.57 48.08,-97.11 47.95,-97.23 47.32,-97.23 47.19,-97.11 47.19,-96.57 46.89,-96.27 46,-96.27 45.69,-96.57 45.69,-97.11 45.57,-97.23 44.93,-97.23 44.8,-97.11 44.8,-96.57 44.5,-96.27 43.61,-96.27 43.31,-96.57 43.31,-97.11 43.18,-97.23 42.54,-97.23 42.42,-97.11 42.42,-96.57 42.11,-96.27 41.22,-96.27 40.92,-96.57 40.92,-97.11 40.79,-97.23 40.16,-97.23 40.03,-97.11 40.03,-96.5 39.72,-96.19 38.84,-96.19 38.53,-96.5 38.53,-97.11 38.4,-97.23 37.77,-97.23 37.64,-97.11 37.64,-96.5 37.34,-96.19 36.45,-96.19 36.14,-96.5 36.14,-97.11 36.02,-97.23 35.38,-97.23 35.25,-97.11 35.25,-96.5 34.95,-96.19 34.06,-96.19 33.76,-96.5 33.76,-97.11 33.63,-97.23 32.99,-97.23 32.87,-97.11 32.87,-96.5 32.56,-96.19 31.67,-96.19 31.37,-96.5 31.37,-97.11 31.24,-97.23 30.61,-97.23 30.48,-97.11 30.48,-96.5 30.17,-96.19 29.29,-96.19 28.98,-96.5 28.98,-97.11 28.85,-97.23 28.22,-97.23 28.09,-97.11 28.09,-96.5 27.79,-96.19 26.9,-96.19 26.59,-96.5 26.59,-97.11 26.47,-97.23 25.83,-97.23 25.7,-97.11 25.7,-96.5 25.4,-96.19 24.51,-96.19 24.21,-96.5 24.21,-97.11 24.08,-97.23 23.44,-97.23 23.32,-97.11 23.32,-96.5 23.01,-96.19 22.12,-96.19 21.82,-96.5 21.82,-97.11 21.69,-97.23 21.06,-97.23 20.93,-97.11 20.93,-96.5 20.62,-96.19 19.74,-96.19 19.43,-96.5 19.43,-97.11 19.3,-97.23 18.67,-97.23 18.54,-97.11 18.54,-96.5 18.24,-96.19 17.35,-96.19 17.04,-96.5 17.04,-97.11 16.92,-97.23 16.28,-97.23 15.8,-96.75 12.94,-96.75 12.76,-96.57 Z_85D_BOT.2
